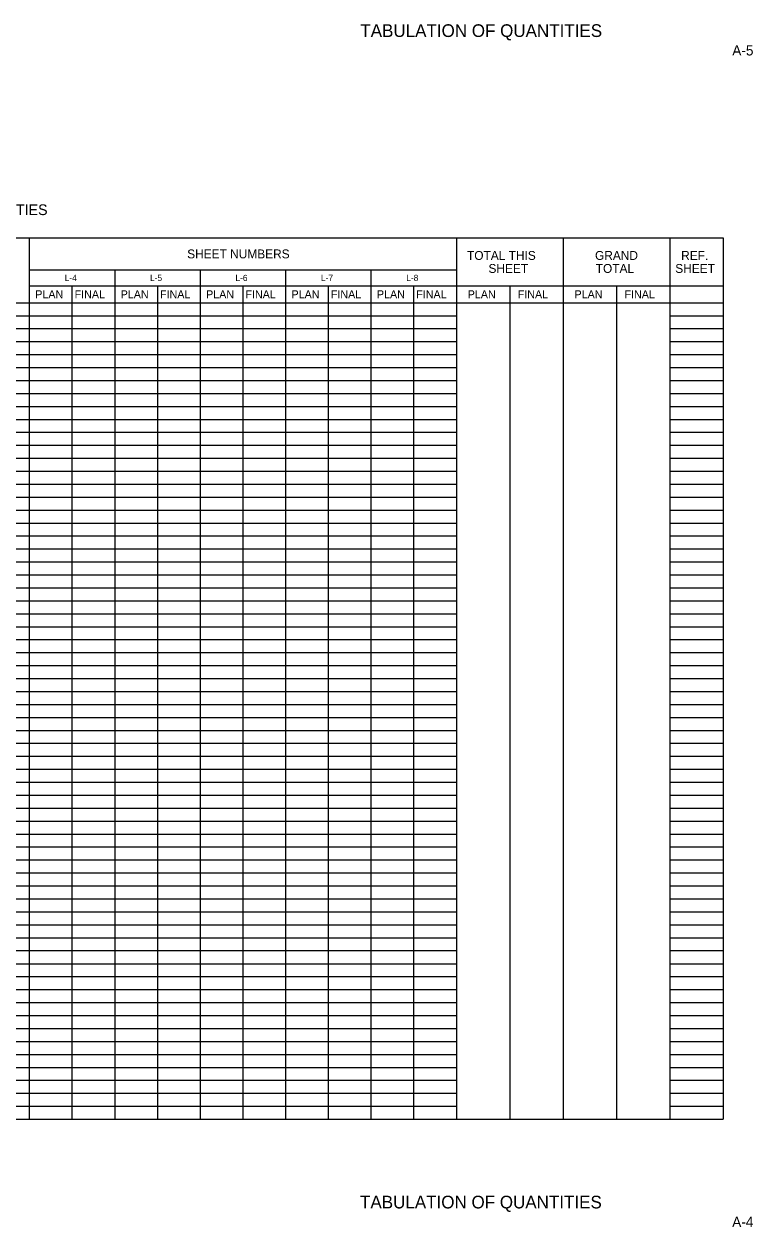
# Model space of a CAD drawing. Extents: x 56 to 1513, y -69 to 5602.
# Drawn here: x 796 to 1513, y -69 to 1115 of the extents above; entities that cross this region are included whole.
import ezdxf

# ---------------------------------------------------------------- set-up
doc = ezdxf.new("R2010")
doc.units = 0
for name, color, linetype in [('Logo_dp', 7, 'Continuous'), ('SheetLines_dp', 7, 'Continuous'), ('TextCurveData', 7, 'Continuous'), ('TextMinor', 7, 'Continuous'), ('TextMisc', 7, 'Continuous'), ('TextNotes', 7, 'Continuous')]:
    doc.layers.add(name, color=color, linetype=linetype)

msp = doc.modelspace()

# ---------------------------------------------------------------- linework, layer by layer
at = {"layer": 'SheetLines_dp'}
for p, q in [((801.3, 904.4), (801.3, 857.2)), ((801.3, 904.4), (801.3, 37.4)), ((1221.3, 904.4), (1221.3, 37.4)), ((1221.3, 904.4), (1221.3, 37.4)), ((1326.3, 904.4), (1326.3, 37.4)), ((1431.3, 904.4), (1431.3, 37.4)), ((1483.8, 904.4), (1483.8, 37.4)), ((801.3, 872.9), (1221.3, 872.9)), ((801.3, 872.9), (1221.3, 872.9)), ((885.3, 872.9), (885.3, 37.4)), ((885.3, 872.9), (885.3, 857.2)), ((969.3, 872.9), (969.3, 37.4)), ((969.3, 872.9), (969.3, 37.4)), ((1053.3, 872.9), (1053.3, 37.4)), ((1053.3, 872.9), (1053.3, 37.4)), ((1137.3, 872.9), (1137.3, 37.4)), ((1137.3, 872.9), (1137.3, 37.4)), ((801.3, 857.2), (1483.8, 857.2)), ((1221.3, 857.2), (1483.8, 857.2)), ((1326.3, 857.2), (1326.3, 37.4)), ((55.8, 840.7), (1483.8, 840.7)), ((55.8, 840.7), (1483.8, 840.7)), ((801.3, 840.7), (801.3, 37.4)), ((885.3, 840.7), (885.3, 37.4)), ((1431.3, 840.7), (1431.3, 37.4))]:
    msp.add_line(p, q, dxfattribs=at)
at = {"layer": 'TextMinor'}
for p, q in [((55.8, 904.4), (1431.3, 904.4)), ((55.8, 904.4), (1483.8, 904.4)), ((55.8, 37.4), (1483.8, 37.4))]:
    msp.add_line(p, q, dxfattribs=at)
at = {"layer": 'TextMisc'}
for p, q in [((843.3, 857.2), (843.3, 37.4)), ((843.3, 857.2), (843.3, 37.4)), ((885.3, 857.2), (885.3, 840.7)), ((927.3, 857.2), (927.3, 37.4)), ((927.3, 857.2), (927.3, 37.4)), ((1011.3, 857.2), (1011.3, 37.4)), ((1011.3, 857.2), (1011.3, 37.4)), ((1095.3, 857.2), (1095.3, 37.4)), ((1095.3, 857.2), (1095.3, 37.4)), ((1179.3, 857.2), (1179.3, 37.4)), ((1179.3, 857.2), (1179.3, 37.4)), ((1273.8, 857.2), (1273.8, 37.4)), ((1273.8, 857.2), (1273.8, 37.4)), ((1378.8, 857.2), (1378.8, 37.4)), ((1378.8, 857.2), (1378.8, 37.4)), ((55.8, 827.9), (1221.3, 827.9)), ((55.8, 827.9), (1221.3, 827.9)), ((1431.3, 827.9), (1483.8, 827.9)), ((1431.3, 827.9), (1483.8, 827.9)), ((55.8, 815.2), (1221.3, 815.2)), ((55.8, 815.2), (1221.3, 815.2)), ((1431.3, 815.2), (1483.8, 815.2)), ((1431.3, 815.2), (1483.8, 815.2)), ((55.8, 802.4), (1221.3, 802.4)), ((55.8, 802.4), (1221.3, 802.4)), ((1431.3, 802.4), (1483.8, 802.4)), ((1431.3, 802.4), (1483.8, 802.4)), ((55.8, 789.7), (1221.3, 789.7)), ((55.8, 789.7), (1221.3, 789.7)), ((1431.3, 789.7), (1483.8, 789.7)), ((1431.3, 789.7), (1483.8, 789.7)), ((55.8, 776.9), (1221.3, 776.9)), ((55.8, 776.9), (1221.3, 776.9)), ((1431.3, 776.9), (1483.8, 776.9)), ((1431.3, 776.9), (1483.8, 776.9)), ((55.8, 764.2), (1221.3, 764.2)), ((55.8, 764.2), (1221.3, 764.2)), ((1431.3, 764.2), (1483.8, 764.2)), ((1431.3, 764.2), (1483.8, 764.2)), ((55.8, 751.4), (1221.3, 751.4)), ((55.8, 751.4), (1221.3, 751.4)), ((1431.3, 751.4), (1483.8, 751.4)), ((1431.3, 751.4), (1483.8, 751.4)), ((55.8, 738.7), (1221.3, 738.7)), ((55.8, 738.7), (1221.3, 738.7)), ((1431.3, 738.7), (1483.8, 738.7)), ((1431.3, 738.7), (1483.8, 738.7)), ((55.8, 725.9), (1221.3, 725.9)), ((55.8, 725.9), (1221.3, 725.9)), ((1431.3, 725.9), (1483.8, 725.9)), ((1431.3, 725.9), (1483.8, 725.9)), ((55.8, 713.2), (1221.3, 713.2)), ((55.8, 713.2), (1221.3, 713.2)), ((1431.3, 713.2), (1483.8, 713.2)), ((1431.3, 713.2), (1483.8, 713.2)), ((55.8, 700.4), (1221.3, 700.4)), ((55.8, 700.4), (1221.3, 700.4)), ((1431.3, 700.4), (1483.8, 700.4)), ((1431.3, 700.4), (1483.8, 700.4)), ((55.8, 687.7), (1221.3, 687.7)), ((55.8, 687.7), (1221.3, 687.7)), ((1431.3, 687.7), (1483.8, 687.7)), ((1431.3, 687.7), (1483.8, 687.7)), ((55.8, 674.9), (1221.3, 674.9)), ((55.8, 674.9), (1221.3, 674.9)), ((1431.3, 674.9), (1483.8, 674.9)), ((1431.3, 674.9), (1483.8, 674.9)), ((55.8, 662.2), (1221.3, 662.2)), ((55.8, 662.2), (1221.3, 662.2)), ((1431.3, 662.2), (1483.8, 662.2)), ((1431.3, 662.2), (1483.8, 662.2)), ((55.8, 649.4), (1221.3, 649.4)), ((55.8, 649.4), (1221.3, 649.4)), ((1431.3, 649.4), (1483.8, 649.4)), ((1431.3, 649.4), (1483.8, 649.4)), ((55.8, 636.7), (1221.3, 636.7)), ((55.8, 636.7), (1221.3, 636.7)), ((1431.3, 636.7), (1483.8, 636.7)), ((1431.3, 636.7), (1483.8, 636.7)), ((55.8, 623.9), (1221.3, 623.9)), ((55.8, 623.9), (1221.3, 623.9)), ((1431.3, 623.9), (1483.8, 623.9)), ((1431.3, 623.9), (1483.8, 623.9)), ((55.8, 611.2), (1221.3, 611.2)), ((55.8, 611.2), (1221.3, 611.2)), ((1431.3, 611.2), (1483.8, 611.2)), ((1431.3, 611.2), (1483.8, 611.2)), ((55.8, 598.4), (1221.3, 598.4)), ((55.8, 598.4), (1221.3, 598.4)), ((1431.3, 598.4), (1483.8, 598.4)), ((1431.3, 598.4), (1483.8, 598.4)), ((55.8, 585.7), (1221.3, 585.7)), ((55.8, 585.7), (1221.3, 585.7)), ((1431.3, 585.7), (1483.8, 585.7)), ((1431.3, 585.7), (1483.8, 585.7)), ((55.8, 572.9), (1221.3, 572.9)), ((55.8, 572.9), (1221.3, 572.9)), ((1431.3, 572.9), (1483.8, 572.9)), ((1431.3, 572.9), (1483.8, 572.9)), ((55.8, 560.2), (1221.3, 560.2)), ((55.8, 560.2), (1221.3, 560.2)), ((1431.3, 560.2), (1483.8, 560.2)), ((1431.3, 560.2), (1483.8, 560.2)), ((55.8, 547.4), (1221.3, 547.4)), ((55.8, 547.4), (1221.3, 547.4)), ((1431.3, 547.4), (1483.8, 547.4)), ((1431.3, 547.4), (1483.8, 547.4)), ((55.8, 534.7), (1221.3, 534.7)), ((55.8, 534.7), (1221.3, 534.7)), ((1431.3, 534.7), (1483.8, 534.7)), ((1431.3, 534.7), (1483.8, 534.7)), ((55.8, 521.9), (1221.3, 521.9)), ((55.8, 521.9), (1221.3, 521.9)), ((1431.3, 521.9), (1483.8, 521.9)), ((1431.3, 521.9), (1483.8, 521.9)), ((55.8, 509.2), (1221.3, 509.2)), ((55.8, 509.2), (1221.3, 509.2)), ((1431.3, 509.2), (1483.8, 509.2)), ((1431.3, 509.2), (1483.8, 509.2)), ((55.8, 496.4), (1221.3, 496.4)), ((55.8, 496.4), (1221.3, 496.4)), ((1431.3, 496.4), (1483.8, 496.4)), ((1431.3, 496.4), (1483.8, 496.4)), ((55.8, 483.7), (1221.3, 483.7)), ((55.8, 483.7), (1221.3, 483.7)), ((1431.3, 483.7), (1483.8, 483.7)), ((1431.3, 483.7), (1483.8, 483.7)), ((55.8, 470.9), (1221.3, 470.9)), ((55.8, 470.9), (1221.3, 470.9)), ((1431.3, 470.9), (1483.8, 470.9)), ((1431.3, 470.9), (1483.8, 470.9)), ((55.8, 458.2), (1221.3, 458.2)), ((55.8, 458.2), (1221.3, 458.2)), ((1431.3, 458.2), (1483.8, 458.2)), ((1431.3, 458.2), (1483.8, 458.2)), ((55.8, 445.4), (1221.3, 445.4)), ((55.8, 445.4), (1221.3, 445.4)), ((1431.3, 445.4), (1483.8, 445.4)), ((1431.3, 445.4), (1483.8, 445.4)), ((55.8, 432.7), (1221.3, 432.7)), ((55.8, 432.7), (1221.3, 432.7)), ((1431.3, 432.7), (1483.8, 432.7)), ((1431.3, 432.7), (1483.8, 432.7)), ((55.8, 419.9), (1221.3, 419.9)), ((55.8, 419.9), (1221.3, 419.9)), ((1431.3, 419.9), (1483.8, 419.9)), ((1431.3, 419.9), (1483.8, 419.9)), ((55.8, 407.2), (1221.3, 407.2)), ((55.8, 407.2), (1221.3, 407.2)), ((1431.3, 407.2), (1483.8, 407.2)), ((1431.3, 407.2), (1483.8, 407.2)), ((55.8, 394.4), (1221.3, 394.4)), ((55.8, 394.4), (1221.3, 394.4)), ((1431.3, 394.4), (1483.8, 394.4)), ((1431.3, 394.4), (1483.8, 394.4)), ((55.8, 381.7), (1221.3, 381.7)), ((55.8, 381.7), (1221.3, 381.7)), ((1431.3, 381.7), (1483.8, 381.7)), ((1431.3, 381.7), (1483.8, 381.7)), ((55.8, 368.9), (1221.3, 368.9)), ((55.8, 368.9), (1221.3, 368.9)), ((1431.3, 368.9), (1483.8, 368.9)), ((1431.3, 368.9), (1483.8, 368.9)), ((55.8, 356.2), (1221.3, 356.2)), ((55.8, 356.2), (1221.3, 356.2)), ((1431.3, 356.2), (1483.8, 356.2)), ((1431.3, 356.2), (1483.8, 356.2)), ((55.8, 343.4), (1221.3, 343.4)), ((55.8, 343.4), (1221.3, 343.4)), ((1431.3, 343.4), (1483.8, 343.4)), ((1431.3, 343.4), (1483.8, 343.4)), ((55.8, 330.7), (1221.3, 330.7)), ((55.8, 330.7), (1221.3, 330.7)), ((1431.3, 330.7), (1483.8, 330.7)), ((1431.3, 330.7), (1483.8, 330.7)), ((55.8, 317.9), (1221.3, 317.9)), ((55.8, 317.9), (1221.3, 317.9)), ((1431.3, 317.9), (1483.8, 317.9)), ((1431.3, 317.9), (1483.8, 317.9)), ((55.8, 305.2), (1221.3, 305.2)), ((55.8, 305.2), (1221.3, 305.2)), ((1431.3, 305.2), (1483.8, 305.2)), ((1431.3, 305.2), (1483.8, 305.2)), ((55.8, 292.4), (1221.3, 292.4)), ((55.8, 292.4), (1221.3, 292.4)), ((1431.3, 292.4), (1483.8, 292.4)), ((1431.3, 292.4), (1483.8, 292.4)), ((55.8, 279.7), (1221.3, 279.7)), ((55.8, 279.7), (1221.3, 279.7)), ((1431.3, 279.7), (1483.8, 279.7)), ((1431.3, 279.7), (1483.8, 279.7)), ((55.8, 266.9), (1221.3, 266.9)), ((55.8, 266.9), (1221.3, 266.9)), ((1431.3, 266.9), (1483.8, 266.9)), ((1431.3, 266.9), (1483.8, 266.9)), ((55.8, 254.2), (1221.3, 254.2)), ((55.8, 254.2), (1221.3, 254.2)), ((1431.3, 254.2), (1483.8, 254.2)), ((1431.3, 254.2), (1483.8, 254.2)), ((55.8, 241.4), (1221.3, 241.4)), ((55.8, 241.4), (1221.3, 241.4)), ((1431.3, 241.4), (1483.8, 241.4)), ((1431.3, 241.4), (1483.8, 241.4)), ((55.8, 228.7), (1221.3, 228.7)), ((55.8, 228.7), (1221.3, 228.7)), ((1431.3, 228.7), (1483.8, 228.7)), ((1431.3, 228.7), (1483.8, 228.7)), ((55.8, 215.9), (1221.3, 215.9)), ((55.8, 215.9), (1221.3, 215.9)), ((1431.3, 215.9), (1483.8, 215.9)), ((1431.3, 215.9), (1483.8, 215.9)), ((55.8, 203.2), (1221.3, 203.2)), ((55.8, 203.2), (1221.3, 203.2)), ((1431.3, 203.2), (1483.8, 203.2)), ((1431.3, 203.2), (1483.8, 203.2)), ((55.8, 190.4), (1221.3, 190.4)), ((55.8, 190.4), (1221.3, 190.4)), ((1431.3, 190.4), (1483.8, 190.4)), ((1431.3, 190.4), (1483.8, 190.4)), ((55.8, 177.7), (1221.3, 177.7)), ((55.8, 177.7), (1221.3, 177.7)), ((1431.3, 177.7), (1483.8, 177.7)), ((1431.3, 177.7), (1483.8, 177.7)), ((55.8, 164.9), (1221.3, 164.9)), ((55.8, 164.9), (1221.3, 164.9)), ((1431.3, 164.9), (1483.8, 164.9)), ((1431.3, 164.9), (1483.8, 164.9)), ((55.8, 152.2), (1221.3, 152.2)), ((55.8, 152.2), (1221.3, 152.2)), ((1431.3, 152.2), (1483.8, 152.2)), ((1431.3, 152.2), (1483.8, 152.2)), ((55.8, 139.4), (1221.3, 139.4)), ((55.8, 139.4), (1221.3, 139.4)), ((1431.3, 139.4), (1483.8, 139.4)), ((1431.3, 139.4), (1483.8, 139.4)), ((55.8, 126.7), (1221.3, 126.7)), ((55.8, 126.7), (1221.3, 126.7)), ((1431.3, 126.7), (1483.8, 126.7)), ((1431.3, 126.7), (1483.8, 126.7)), ((55.8, 113.9), (1221.3, 113.9)), ((55.8, 113.9), (1221.3, 113.9)), ((1431.3, 113.9), (1483.8, 113.9)), ((1431.3, 113.9), (1483.8, 113.9)), ((55.8, 101.2), (1221.3, 101.2)), ((55.8, 101.2), (1221.3, 101.2)), ((1431.3, 101.2), (1483.8, 101.2)), ((1431.3, 101.2), (1483.8, 101.2)), ((55.8, 88.4), (1221.3, 88.4)), ((55.8, 88.4), (1221.3, 88.4)), ((1431.3, 88.4), (1483.8, 88.4)), ((1431.3, 88.4), (1483.8, 88.4)), ((55.8, 75.7), (1221.3, 75.7)), ((55.8, 75.7), (1221.3, 75.7)), ((1431.3, 75.7), (1483.8, 75.7)), ((1431.3, 75.7), (1483.8, 75.7)), ((55.8, 62.9), (1221.3, 62.9)), ((55.8, 62.9), (1221.3, 62.9)), ((1431.3, 62.9), (1483.8, 62.9)), ((1431.3, 62.9), (1483.8, 62.9)), ((55.8, 50.2), (1221.3, 50.2)), ((55.8, 50.2), (1221.3, 50.2)), ((1431.3, 50.2), (1483.8, 50.2)), ((1431.3, 50.2), (1483.8, 50.2))]:
    msp.add_line(p, q, dxfattribs=at)

# ---------------------------------------------------------------- texts
at = {"layer": 'Logo_dp'}
for s, p in [('A-5', (1492.7, 1083.9)), ('A-4', (1492.6, -68.6))]:
    msp.add_text(s, height=10, dxfattribs=at).set_placement(p)
at = {"layer": 'TextCurveData'}
for s, height, p in [('TABULATION  OF  QUANTITIES', 10.5, (611.8, 926.9)), ('SHEET NUMBERS', 8.75, (956.6, 884.3)), ('TOTAL THIS', 8.75, (1231.8, 882.8)), ('GRAND', 8.75, (1357.7, 882.8)), ('REF.', 8.75, (1442.4, 882.8)), ('SHEET', 8.75, (1252.9, 870)), ('TOTAL', 8.75, (1358.4, 870)), ('SHEET', 8.75, (1436.6, 870)), ('L-4', 6.12, (836.2, 862)), ('L-5', 6.12, (920.1, 862)), ('L-6', 6.12, (1004.1, 862)), ('L-7', 6.12, (1088.2, 862)), ('L-8', 6.12, (1172.1, 862)), ('PLAN', 7.88, (807.2, 845)), ('FINAL', 7.88, (845.9, 845)), ('PLAN', 7.88, (891.2, 845)), ('FINAL', 7.88, (929.9, 845)), ('PLAN', 7.88, (975.2, 845)), ('FINAL', 7.88, (1013.9, 845)), ('PLAN', 7.88, (1059.2, 845)), ('FINAL', 7.88, (1097.9, 845)), ('PLAN', 7.88, (1143.2, 845)), ('FINAL', 7.88, (1181.9, 845)), ('PLAN', 7.88, (1232.5, 845)), ('FINAL', 7.88, (1281.7, 845)), ('PLAN', 7.88, (1337.5, 845)), ('FINAL', 7.88, (1386.7, 845))]:
    msp.add_text(s, height=height, dxfattribs=at).set_placement(p)
at = {"layer": 'TextNotes'}
for p in [(1126.9, 1102.1), (1126.6, -50.4)]:
    msp.add_text('TABULATION OF QUANTITIES ', height=12.5, dxfattribs=at).set_placement(p)

doc.saveas('drawing.dxf')
